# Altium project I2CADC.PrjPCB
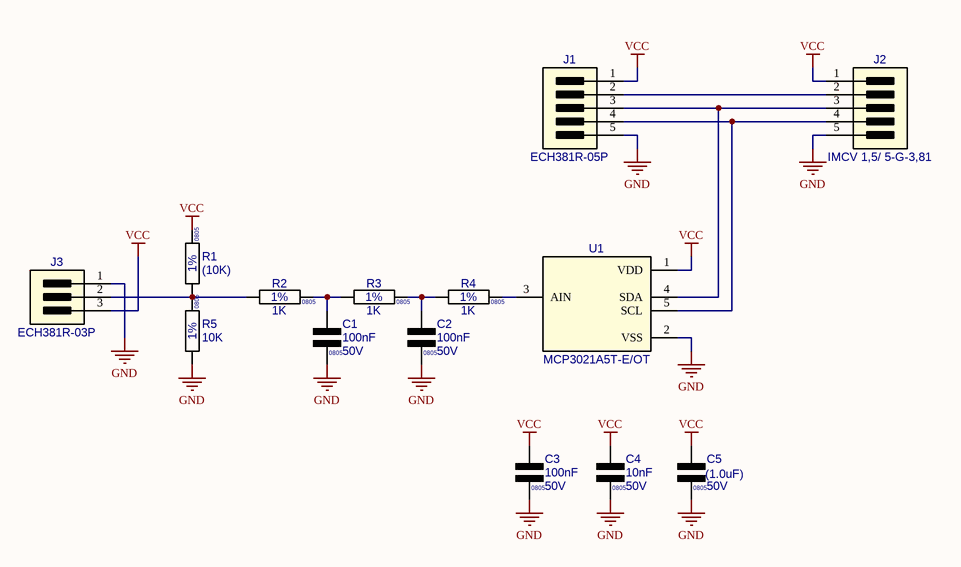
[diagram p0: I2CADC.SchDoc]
Version: 01.00; Spec_Solder Mask: GREEN; Spec_Silkscreen: WHITE EPOXY; Spec_PCB Thickness: 1.60mm; Spec_Cu Thickness: 35um; SCH_Title: I2CADC; SCH_SheetTotal: 1; SCH_Reviewed: DG; SCH_QA: -; SCH_Number: -; SCH_FILENAME: I2CADC.SCH; SCH_ECR: -; SCH_DRAWN: DG; SCH_DocRev: 01; SCH_Date: 25/06/2015; SCH_CM: -; SCH_Approved: DG; PCB_TITLE: I2CADC PCB; PCB_Plot File [Assy]: I2CADC [Assy]; PCB_Plot File: I2CADC [Panel]; PCB_ECRNo: -; PCB_Drawn: EDM; PCB_Drawing Number: -; PCB_DocRevision: 01; PCB_Company Name: AGRIGEL
1 sheet, 14 parts. Net scope: global (net labels, ports and power ports of the same name join across sheets).
Board files: I2CADC.PcbDoc, I2CADC [Assy].PcbDoc, I2CADC [Panel].PcbDoc

## Sheet I2CADC.SchDoc: #
size A3; ApprovedBy: #; DrawnBy: #; DocumentNumber: #; Revision: #; SheetNumber: 1; DocumentRevision: #; Reviewed: #; QA: #; CM: #; ECR: #; PageSetup: Record=PageOptions¦CenterHorizontal=True¦CenterVertical=True¦PrintScale=0.97¦XCorrection=1.00¦YCorrection=1.00¦PrintKind=1¦BorderSize=5000000¦LeftOffset=0¦BottomOffset=0¦Orientation=2¦PaperLength=1000¦PaperWidth=1000¦Scale=100¦PaperSource=7¦PrintQuality=-4¦MediaType=1¦DitherType=10¦PaperKind=A3¦PrintScaleMode=1

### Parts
C1  value 100nF  Voltage: 50V  Text1: 0805  [CAPC0805X110N]  (hidden comment: 100nF_C0805_50V_10%_X7R)
C2  value 100nF  Voltage: 50V  Text1: 0805  [CAPC0805X110N]  (hidden comment: 100nF_C0805_50V_10%_X7R)
C3  value 100nF  Voltage: 50V  Text1: 0805  [CAPC0805X110N]  (hidden comment: 100nF_C0805_50V_10%_X7R)
C4  value 10nF  Voltage: 50V  Text1: 0805  [CAPC0805X110N]  (hidden comment: 10nF_C0805_50V_10%_X7R)
C5  value (1.0uF)  Voltage: 50V  Text1: 0805  [CAPC0805X110N]  (hidden comment: 1uF_C0805_50V_10%_X7R-DNF)
J1  ECH381R-05P  [ECH381R-05P]
J2  IMCV 1,5/ 5-G-3,81  [IMCV 1,5/ 5-G-3,81]
J3  ECH381R-03P  [ECH381R-03P]
R1  value (10K)  Tol: 1%  Text1: 0805  [RESC0805X65N]  (hidden comment: 10K_R0805_1%-DNF)
R2  value 1K  Tol: 1%  Text1: 0805  [RESC0805X65N]  (hidden comment: 1K_R0805_1%)
R3  value 1K  Tol: 1%  Text1: 0805  [RESC0805X65N]  (hidden comment: 1K_R0805_1%)
R4  value 1K  Tol: 1%  Text1: 0805  [RESC0805X65N]  (hidden comment: 1K_R0805_1%)
R5  value 10K  Tol: 1%  Text1: 0805  [RESC0805X65N]  (hidden comment: 10K_R0805_1%)
U1  MCP3021A5T-E/OT  [SOT23-5]

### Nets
GND: C1.2 C2.2 C3.2 C4.2 C5.2 J1.5 J2.5 J3.1 R5.2 U1.2(VSS)
VCC: C3.1 C4.1 C5.1 J1.1 J2.1 J3.3 R1.1 U1.1(VDD)
NetC1_1: C1.1 R2.2 R3.1
NetC2_1: C2.1 R3.2 R4.1
NetJ1_2: J1.2 J2.2
NetJ1_3: J1.3 J2.3 U1.4(SDA)
NetJ1_4: J1.4 J2.4 U1.5(SCL)
NetJ3_2: J3.2 R1.2 R2.1 R5.1
NetR4_2: R4.2 U1.3(AIN)

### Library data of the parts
C1-C3 = 100nF_0805N_50V_10%_X7R_V: Cap Ceramic X7R; Manufacturer: Various; Part Number: 100nF 0805 50V 10% X7R; Board Tech: SMD; EDM-PN: CAP42; Tol: 10%; Reutech PN: 5910-CA-0122
C4 = 10nF_0805N_50V_10%_X7R_V: Cap Ceramic X7R; Manufacturer: Various; Part Number: 10nF 0805 50V 10% X7R; Board Tech: SMD; EDM-PN: CAP5; Tol: 10%
C5 = 1uF_0805N_50V_10%_X7R_V-DNF: Cap Ceramic X7R - Do not Fit; Manufacturer: Various; Part Number: DNF - 1.0uF 0805 50V 10% X7R; Board Tech: SMD; EDM-PN: CAP375; Tol: 10%
J1 = ECH381R-05P: Header Pluggable 3.81mm Rt Angle; Manufacturer: Dinkle; Board Tech: THP
J2 = IMCV 1,5/ 5-G-3,81: Header Pluggable 3.81mm Vertical Female; Manufacturer: Phoenix; Part Number: 1875454; Board Tech: THP
J3 = ECH381R-03P: Header Pluggable 3.81mm Rt Angle; Manufacturer: Dinkle; Board Tech: THP
R1 = 10K_0805_v-DNF: Resistor Chip SMD - Do not Fit; Manufacturer: Various; Part Number: DNF - 10K 0805 1%; Watt: 125mW; EDM-PN: DNF
R2-R4 = 1K_0805_H: Resistor Chip SMD; Manufacturer: Various; Part Number: 1K 0805 1%; Watt: 125mW; EDM-PN: RES14
R5 = 10K_0805_V: Resistor Chip SMD; Manufacturer: Various; Part Number: 10K 0805 1%; Watt: 125mW; EDM-PN: RES8
U1 = MCP3021A5T-E/OT_SOT23: IC 10-Bit A/D Converter with I2C; Manufacturer: Microchip; Board Tech: SMD

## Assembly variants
Variant of I2CADC: not fitted C5 R1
